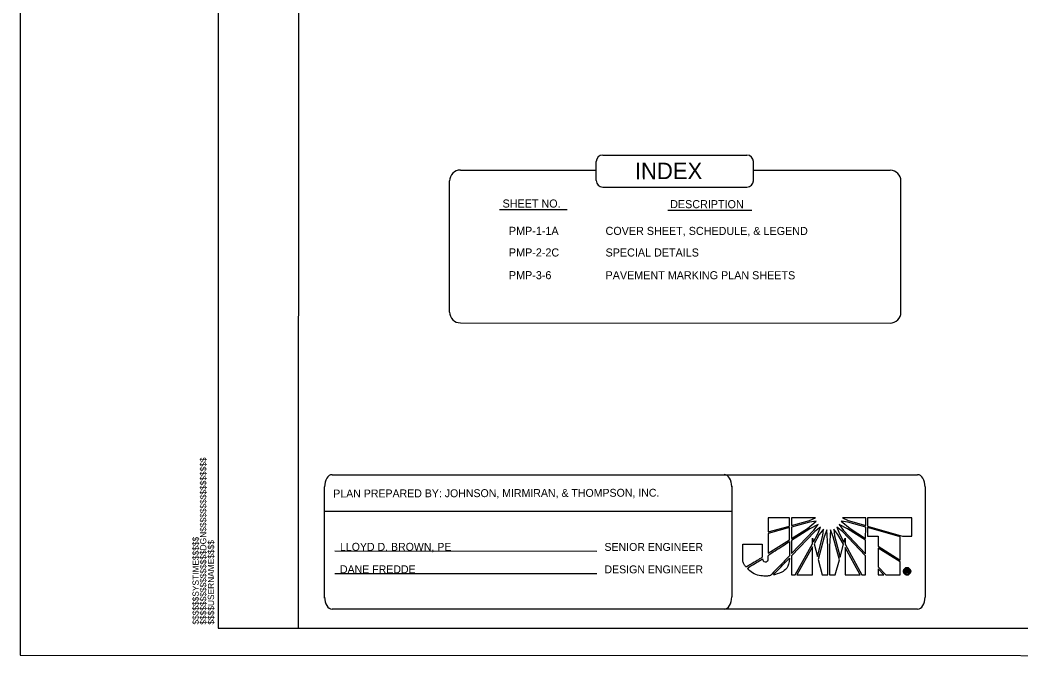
# Model space of a CAD drawing. Extents: x 50667 to 52386, y 46650 to 50479.
# Drawn here: x 50703 to 51544, y 49383 to 49917 of the extents above; entities that cross this region are included whole.
import ezdxf

# ---------------------------------------------------------------- set-up
doc = ezdxf.new("R2010")
doc.units = 0
for name, color, linetype in [('Default', 7, 'Continuous'), ('DEV TUBULAR MARKER SECTIONAL VIEW CELL', 7, 'Continuous'), ('Exist Utilities Power Pole Text Tag Number', 7, 'Continuous'), ('Prop Vertical Profile Ditch Grade Left', 7, 'Continuous'), ('Prop VPI Ditch Grade Left Label', 7, 'Continuous'), ('TSCONFLICT', 7, 'Continuous')]:
    doc.layers.add(name, color=color, linetype=linetype)

msp = doc.modelspace()

# ---------------------------------------------------------------- linework, layer by layer
at = {"layer": 'Default'}
for p, q in [((50965.09, 49534.88), (51457.31, 49534.93)), ((50958.71, 49431.24), (50958.68, 49524.68)), ((51301.08, 49525.65), (51301.1, 49432.21)), ((51463.72, 49524.69), (51463.73, 49432.13)), ((50958.67, 49504.26), (51301.11, 49504.41)), ((51349.65, 49498.59), (51331.88, 49498.58)), ((51331.88, 49498.58), (51331.88, 49486.8)), ((51349.65, 49491.73), (51349.65, 49498.59)), ((51371.49, 49498.68), (51351.5, 49498.68)), ((51351.5, 49498.68), (51351.5, 49492.31)), ((51351.5, 49492.31), (51366.39, 49496.42)), ((51366.39, 49495.04), (51351.5, 49490.93)), ((51364.84, 49489.76), (51372.2, 49495.75)), ((51366.39, 49496.42), (51371.49, 49498.68)), ((51372.2, 49495.75), (51366.39, 49495.04)), ((51373.67, 49492.99), (51366.89, 49489.56)), ((51370.24, 49488.18), (51373.67, 49492.99)), ((51391.58, 49492.99), (51395.01, 49488.09)), ((51398.44, 49489.56), (51391.58, 49492.99)), ((51393.14, 49495.75), (51400.58, 49489.65)), ((51398.62, 49495.04), (51393.14, 49495.75)), ((51413.84, 49498.59), (51394.13, 49498.68)), ((51394.13, 49498.68), (51399.12, 49496.33)), ((51413.84, 49490.85), (51398.62, 49495.04)), ((51399.12, 49496.33), (51413.84, 49492.2)), ((51413.84, 49492.2), (51413.84, 49498.59)), ((51452.57, 49498.69), (51415.22, 49498.68)), ((51415.22, 49498.68), (51415.22, 49491.82)), ((51452.57, 49483.38), (51452.57, 49498.69)), ((51331.88, 49486.8), (51349.65, 49491.73)), ((51349.65, 49490.44), (51331.88, 49485.45)), ((51331.88, 49485.45), (51331.88, 49468.88)), ((51349.65, 49480.14), (51349.65, 49490.44)), ((51351.5, 49490.93), (51351.5, 49481.32)), ((51351.5, 49481.32), (51364.84, 49489.76)), ((51366.89, 49489.56), (51351.5, 49479.76)), ((51351.5, 49468.68), (51370.24, 49488.18)), ((51371, 49487.21), (51351.5, 49466.8)), ((51369.83, 49478.39), (51373.55, 49485.16)), ((51374.75, 49484.75), (51370.32, 49476.71)), ((51375.72, 49490.85), (51371, 49487.21)), ((51373.55, 49485.16), (51375.72, 49490.85)), ((51378.27, 49489.27), (51374.75, 49484.75)), ((51377.77, 49483.78), (51378.27, 49489.27)), ((51381.2, 49488.47), (51378.77, 49482.79)), ((51381.97, 49474.46), (51381.2, 49488.47)), ((51384.13, 49488.47), (51383.23, 49474.46)), ((51386.48, 49482.79), (51384.13, 49488.47)), ((51386.98, 49489.27), (51387.57, 49483.58)), ((51390.41, 49484.75), (51386.98, 49489.27)), ((51389.5, 49490.85), (51391.67, 49485.16)), ((51394.22, 49487.21), (51389.5, 49490.85)), ((51395.01, 49476.42), (51390.41, 49484.75)), ((51391.67, 49485.16), (51395.48, 49478.1)), ((51413.72, 49466.63), (51394.22, 49487.21)), ((51395.01, 49488.09), (51413.72, 49468.48)), ((51413.72, 49479.86), (51398.44, 49489.56)), ((51400.58, 49489.65), (51413.72, 49481.44)), ((51413.72, 49481.44), (51413.84, 49490.85)), ((51415.22, 49491.82), (51415.22, 49491.62)), ((51415.22, 49491.62), (51444.63, 49483.38)), ((51415.22, 49490.56), (51415.22, 49490.44)), ((51442.75, 49482.7), (51415.22, 49490.56)), ((51415.22, 49490.44), (51415.22, 49483.29)), ((51331.88, 49468.88), (51349.65, 49480.14)), ((51351.5, 49479.76), (51351.5, 49468.68)), ((51354.43, 49450.67), (51368.95, 49476.92)), ((51368.95, 49476.92), (51368.95, 49481.61)), ((51368.95, 49481.61), (51369.83, 49478.39)), ((51370.32, 49476.71), (51373.17, 49466.04)), ((51373.17, 49466.04), (51377.77, 49483.78)), ((51378.77, 49482.79), (51373.76, 49463.58)), ((51391.59, 49463.29), (51386.48, 49482.79)), ((51387.57, 49483.58), (51392.17, 49465.63)), ((51392.17, 49465.63), (51395.01, 49476.42)), ((51395.48, 49478.1), (51396.39, 49481.61)), ((51396.39, 49481.61), (51396.39, 49476.42)), ((51396.39, 49476.42), (51410.59, 49450.68)), ((51413.72, 49468.48), (51413.72, 49479.86)), ((51415.22, 49483.29), (51424.34, 49483.29)), ((51424.34, 49483.29), (51424.34, 49474.76)), ((51442.75, 49463.09), (51442.75, 49482.7)), ((51444.63, 49483.38), (51452.57, 49483.38)), ((50967.45, 49470.81), (51187.76, 49470.71)), ((51368.95, 49474.37), (51355.81, 49450.67)), ((51369.07, 49450.68), (51368.95, 49474.37)), ((51381.97, 49450.76), (51381.97, 49474.46)), ((51383.23, 49474.46), (51383.23, 49450.76)), ((51409.12, 49450.77), (51396.39, 49473.87)), ((51396.39, 49473.87), (51396.4, 49450.77)), ((51424.34, 49474.76), (51442.75, 49463.09)), ((51424.34, 49473.29), (51424.34, 49457.4)), ((51442.75, 49461.71), (51424.34, 49473.29)), ((51351.5, 49466.8), (51351.5, 49450.67)), ((51373.76, 49463.58), (51377.1, 49450.76)), ((51388.16, 49450.77), (51391.59, 49463.29)), ((51413.73, 49450.68), (51413.72, 49466.63)), ((51442.75, 49450.68), (51442.75, 49461.71)), ((50967.44, 49451.94), (51187.75, 49451.82)), ((51351.5, 49450.67), (51354.43, 49450.67)), ((51355.81, 49450.67), (51369.07, 49450.68)), ((51377.1, 49450.76), (51381.97, 49450.76)), ((51383.23, 49450.76), (51388.16, 49450.77)), ((51396.4, 49450.77), (51409.12, 49450.77)), ((51410.59, 49450.68), (51413.73, 49450.68)), ((51424.34, 49457.4), (51430.7, 49450.68)), ((51428.94, 49450.68), (51424.34, 49455.67)), ((51424.34, 49455.67), (51424.34, 49450.68)), ((51424.34, 49450.68), (51428.94, 49450.68)), ((51430.7, 49450.68), (51442.75, 49450.68)), ((51447.43, 49452.36), (51447.43, 49455.08)), ((51447.43, 49455.08), (51448.54, 49455.08)), ((51448.05, 49452.36), (51447.43, 49452.36)), ((51448.54, 49454.56), (51448.05, 49454.56)), ((51448.05, 49454.56), (51448.05, 49453.92)), ((51448.05, 49453.92), (51448.54, 49453.92)), ((51448.54, 49453.42), (51448.05, 49453.42)), ((51448.05, 49453.42), (51448.05, 49452.36)), ((51448.54, 49456.68), (51448.54, 49456.12)), ((51448.54, 49456.12), (51448.54, 49456.68)), ((51448.54, 49455.08), (51448.54, 49454.56)), ((51448.54, 49454.56), (51448.54, 49455.08)), ((51448.54, 49455.08), (51448.72, 49455.08)), ((51448.62, 49454.56), (51448.54, 49454.56)), ((51448.54, 49453.92), (51448.54, 49453.42)), ((51448.54, 49453.42), (51448.54, 49453.92)), ((51448.54, 49453.92), (51448.57, 49453.92)), ((51448.57, 49453.42), (51448.54, 49453.42)), ((51448.55, 49451.3), (51448.55, 49450.71)), ((51448.55, 49450.71), (51448.55, 49451.3)), ((51448.55, 49451.3), (51448.57, 49451.3)), ((51448.57, 49450.71), (51448.55, 49450.71)), ((51457.31, 49421.89), (50965.1, 49421.83))]:
    msp.add_line(p, q, dxfattribs=at)
for points in [[(51331.88, 49486.8), (51349.65, 49491.73), (51349.65, 49498.59), (51331.88, 49498.58), (51331.88, 49486.8)], [(51366.39, 49496.42), (51371.49, 49498.68), (51351.5, 49498.68), (51351.5, 49492.31), (51366.39, 49496.42)], [(51351.5, 49490.93), (51351.5, 49481.32), (51364.84, 49489.76), (51372.2, 49495.75), (51366.39, 49495.04), (51351.5, 49490.93)], [(51351.5, 49479.76), (51351.5, 49468.68), (51370.24, 49488.18), (51373.67, 49492.99), (51366.89, 49489.56), (51351.5, 49479.76)], [(51391.58, 49492.99), (51395.01, 49488.09), (51413.72, 49468.48), (51413.72, 49479.86), (51398.44, 49489.56), (51391.58, 49492.99)], [(51393.14, 49495.75), (51400.58, 49489.65), (51413.72, 49481.44), (51413.84, 49490.85), (51398.62, 49495.04), (51393.14, 49495.75)], [(51399.12, 49496.33), (51413.84, 49492.2), (51413.84, 49498.59), (51394.13, 49498.68), (51399.12, 49496.33)], [(51452.57, 49498.69), (51415.22, 49498.68), (51415.22, 49491.82), (51415.22, 49491.62), (51444.63, 49483.38), (51452.57, 49483.38), (51452.57, 49498.69)], [(51331.88, 49468.88), (51349.65, 49480.14), (51349.65, 49490.44), (51331.88, 49485.45), (51331.88, 49468.88)], [(51375.72, 49490.85), (51371, 49487.21), (51351.5, 49466.8), (51351.5, 49450.67), (51354.43, 49450.67), (51368.95, 49476.92), (51368.95, 49481.61), (51369.83, 49478.39), (51373.55, 49485.16), (51375.72, 49490.85)], [(51378.27, 49489.27), (51374.75, 49484.75), (51370.32, 49476.71), (51373.17, 49466.04), (51377.77, 49483.78), (51378.27, 49489.27)], [(51378.77, 49482.79), (51373.76, 49463.58), (51377.1, 49450.76), (51381.97, 49450.76), (51381.97, 49474.46), (51381.2, 49488.47), (51378.77, 49482.79)], [(51384.13, 49488.47), (51383.23, 49474.46), (51383.23, 49450.76), (51388.16, 49450.77), (51391.59, 49463.29), (51386.48, 49482.79), (51384.13, 49488.47)], [(51386.98, 49489.27), (51387.57, 49483.58), (51392.17, 49465.63), (51395.01, 49476.42), (51390.41, 49484.75), (51386.98, 49489.27)], [(51389.5, 49490.85), (51391.67, 49485.16), (51395.48, 49478.1), (51396.39, 49481.61), (51396.39, 49476.42), (51410.59, 49450.68), (51413.73, 49450.68), (51413.72, 49466.63), (51394.22, 49487.21), (51389.5, 49490.85)], [(51415.22, 49490.56), (51415.22, 49490.44), (51415.22, 49483.29), (51424.34, 49483.29), (51424.34, 49474.76), (51442.75, 49463.09), (51442.75, 49482.7), (51415.22, 49490.56)], [(51355.81, 49450.67), (51369.07, 49450.68), (51368.95, 49474.37), (51355.81, 49450.67)], [(51396.4, 49450.77), (51409.12, 49450.77), (51396.39, 49473.87), (51396.4, 49450.77)], [(51424.34, 49473.29), (51424.34, 49457.4), (51430.7, 49450.68), (51442.75, 49450.68), (51442.75, 49461.71), (51424.34, 49473.29), (51424.34, 49473.29)], [(51424.34, 49450.68), (51424.34, 49450.68), (51428.94, 49450.68), (51424.34, 49455.67), (51424.34, 49450.68)], [(51448.54, 49455.08), (51447.43, 49455.08), (51447.43, 49452.36), (51448.05, 49452.36), (51448.05, 49453.42), (51448.54, 49453.42), (51448.54, 49453.92), (51448.05, 49453.92), (51448.05, 49454.56), (51448.54, 49454.56), (51448.54, 49455.08)], [(51449.73, 49453), (51449.73, 49452.86), (51449.75, 49452.76), (51449.75, 49452.66), (51449.83, 49452.36), (51449.26, 49452.36)]]:
    msp.add_lwpolyline(points, dxfattribs=at)
for centre, major_axis, start_param, end_param in [((50965.1, 49524.69), (0, 10.24), 0.000702, 1.571498), ((51294.69, 49524.77), (0, 10.24), 4.713091, 6.283887), ((51457.31, 49524.69), (0, 10.24), 4.713091, 6.283887), ((50965.1, 49432.12), (0, -10.24), 4.713091, 6.283887), ((51294.69, 49432.2), (0, -10.24), 0.000702, 1.571498), ((51457.31, 49432.13), (0, -10.24), 0.000702, 1.571498)]:
    msp.add_ellipse(centre, major_axis=major_axis, ratio=0.62659, start_param=start_param, end_param=end_param, dxfattribs=at)
for points, degree in [([(51326.78, 49476.5), (51326.78, 49476.5), (51310.33, 49476.5), (51310.33, 49476.5), (51310.33, 49476.5), (51310.33, 49466.21), (51310.33, 49466.21), (51310.33, 49466.21), (51310.33, 49465.12), (51310.33, 49465.12), (51310.33, 49461.9), (51311.39, 49459.35), (51313.26, 49457.21), (51313.26, 49457.21), (51326.78, 49465.42), (51326.78, 49465.63), (51326.78, 49465.63), (51326.78, 49476.5), (51326.78, 49476.5)], 3), ([(51326.78, 49476.5), (51326.78, 49476.5), (51310.33, 49476.5), (51310.33, 49476.5), (51310.33, 49476.5), (51310.33, 49466.21), (51310.33, 49466.21), (51310.33, 49466.21), (51310.33, 49465.12), (51310.33, 49465.12), (51310.33, 49461.9), (51311.39, 49459.35), (51313.26, 49457.21), (51313.26, 49457.21), (51326.78, 49465.42), (51326.78, 49465.63), (51326.78, 49465.63), (51326.78, 49476.5), (51326.78, 49476.5)], 3), ([(51329.33, 49461.7), (51328.28, 49461.7), (51327.37, 49462.28), (51326.99, 49464.25), (51326.99, 49464.25), (51314.23, 49456.36), (51314.23, 49456.36), (51318.16, 49452.22), (51324.44, 49449.76), (51329.74, 49449.76), (51331.12, 49449.76), (51332.18, 49449.88), (51333.64, 49450.17), (51333.64, 49450.17), (51349.65, 49466.71), (51349.65, 49466.71), (51349.65, 49466.71), (51349.65, 49478.68), (51349.65, 49478.68), (51349.65, 49478.68), (51331.88, 49467.39), (51331.88, 49467.39), (51331.88, 49462.9), (51330.8, 49461.7), (51329.33, 49461.7)], 3), ([(51329.33, 49461.7), (51328.28, 49461.7), (51327.37, 49462.28), (51326.99, 49464.25), (51326.99, 49464.25), (51314.23, 49456.36), (51314.23, 49456.36), (51318.16, 49452.22), (51324.44, 49449.76), (51329.74, 49449.76), (51331.12, 49449.76), (51332.18, 49449.88), (51333.64, 49450.17), (51333.64, 49450.17), (51349.65, 49466.71), (51349.65, 49466.71), (51349.65, 49466.71), (51349.65, 49478.68), (51349.65, 49478.68), (51349.65, 49478.68), (51331.88, 49467.39), (51331.88, 49467.39), (51331.88, 49462.9), (51330.8, 49461.7), (51329.33, 49461.7)], 3), ([(51349.65, 49464.84), (51349.65, 49464.84), (51335.81, 49450.55), (51335.81, 49450.55), (51342.59, 49452.23), (51349.33, 49456.71), (51349.65, 49464.84)], 3), ([(51349.65, 49464.84), (51349.65, 49464.84), (51335.81, 49450.55), (51335.81, 49450.55), (51342.59, 49452.23), (51349.33, 49456.71), (51349.65, 49464.84)], 3), ([(51448.55, 49450.71), (51447.73, 49450.71), (51447.01, 49451), (51446.42, 49451.6), (51445.83, 49452.16), (51445.53, 49452.88), (51445.53, 49453.72), (51445.53, 49454.56), (51445.83, 49455.28), (51446.42, 49455.82), (51447.01, 49456.39), (51447.7, 49456.68), (51448.54, 49456.68), (51448.54, 49456.68), (51448.54, 49456.12), (51448.54, 49456.12), (51447.88, 49456.12), (51447.31, 49455.89), (51446.84, 49455.45), (51446.37, 49454.98), (51446.12, 49454.39), (51446.12, 49453.72), (51446.12, 49453.05), (51446.37, 49452.46), (51446.84, 49451.99), (51447.31, 49451.52), (51447.88, 49451.3), (51448.55, 49451.3), (51448.55, 49451.3), (51448.55, 49450.71), (51448.55, 49450.71), (51448.55, 49450.71), (51448.55, 49450.71), (51448.55, 49450.71)], 3), ([(51448.55, 49450.71), (51447.73, 49450.71), (51447.01, 49451), (51446.42, 49451.6), (51445.83, 49452.16), (51445.53, 49452.88), (51445.53, 49453.72), (51445.53, 49454.56), (51445.83, 49455.28), (51446.42, 49455.82), (51447.01, 49456.39), (51447.7, 49456.68), (51448.54, 49456.68)], 3), ([(51448.54, 49456.12), (51447.88, 49456.12), (51447.31, 49455.89), (51446.84, 49455.45), (51446.37, 49454.98), (51446.12, 49454.39), (51446.12, 49453.72), (51446.12, 49453.05), (51446.37, 49452.46), (51446.84, 49451.99), (51447.31, 49451.52), (51447.88, 49451.3), (51448.55, 49451.3)], 3), ([(51451.58, 49453.72), (51451.58, 49452.88), (51451.29, 49452.17), (51450.72, 49451.57), (51450.13, 49451), (51449.41, 49450.71), (51448.57, 49450.71), (51448.57, 49450.71), (51448.57, 49450.71), (51448.55, 49450.71), (51448.55, 49450.71), (51448.55, 49451.3), (51448.55, 49451.3), (51448.57, 49451.3), (51448.57, 49451.3), (51448.57, 49451.3), (51449.24, 49451.3), (51449.8, 49451.52), (51450.27, 49451.99), (51450.74, 49452.46), (51450.99, 49453.05), (51450.99, 49453.72), (51450.99, 49454.39), (51450.74, 49454.98), (51450.27, 49455.45), (51449.8, 49455.89), (51449.24, 49456.12), (51448.54, 49456.12), (51448.54, 49456.12), (51448.54, 49456.68), (51448.54, 49456.68), (51449.38, 49456.68), (51450.1, 49456.39), (51450.69, 49455.82), (51451.29, 49455.28), (51451.58, 49454.56), (51451.58, 49453.72), (51451.58, 49453.72), (51451.58, 49453.72), (51451.58, 49453.72)], 3), ([(51448.54, 49456.68), (51449.38, 49456.68), (51450.1, 49456.39), (51450.69, 49455.82), (51451.29, 49455.28), (51451.58, 49454.56), (51451.58, 49453.72)], 3), ([(51448.57, 49451.3), (51449.24, 49451.3), (51449.8, 49451.52), (51450.27, 49451.99), (51450.74, 49452.46), (51450.99, 49453.05), (51450.99, 49453.72), (51450.99, 49454.39), (51450.74, 49454.98), (51450.27, 49455.45), (51449.8, 49455.89), (51449.24, 49456.12), (51448.54, 49456.12)], 3), ([(51448.54, 49453.42), (51448.54, 49453.42), (51448.54, 49453.92), (51448.54, 49453.92), (51448.54, 49453.92), (51448.57, 49453.92), (51448.57, 49453.92), (51448.96, 49453.92), (51449.16, 49454.04), (51449.16, 49454.26), (51449.16, 49454.46), (51448.99, 49454.56), (51448.62, 49454.56), (51448.62, 49454.56), (51448.54, 49454.56), (51448.54, 49454.56), (51448.54, 49454.56), (51448.54, 49455.08), (51448.54, 49455.08), (51448.54, 49455.08), (51448.72, 49455.08), (51448.72, 49455.08), (51449.41, 49455.08), (51449.75, 49454.81), (51449.75, 49454.26), (51449.75, 49454.02), (51449.66, 49453.82), (51449.43, 49453.67), (51449.61, 49453.57), (51449.71, 49453.35), (51449.73, 49453), (51449.73, 49453), (51449.73, 49452.86), (51449.73, 49452.86), (51449.73, 49452.86), (51449.75, 49452.76), (51449.75, 49452.76), (51449.75, 49452.76), (51449.75, 49452.66), (51449.75, 49452.66), (51449.75, 49452.66), (51449.83, 49452.36), (51449.83, 49452.36), (51449.83, 49452.36), (51449.26, 49452.36), (51449.26, 49452.36), (51449.19, 49452.51), (51449.14, 49452.66), (51449.14, 49452.86), (51449.14, 49453.1), (51449.11, 49453.25), (51449.04, 49453.33), (51448.96, 49453.37), (51448.82, 49453.42), (51448.57, 49453.42), (51448.57, 49453.42), (51448.54, 49453.42), (51448.54, 49453.42)], 3), ([(51448.57, 49453.92), (51448.96, 49453.92), (51449.16, 49454.04), (51449.16, 49454.26), (51449.16, 49454.46), (51448.99, 49454.56), (51448.62, 49454.56)], 3), ([(51451.58, 49453.72), (51451.58, 49452.88), (51451.29, 49452.17), (51450.72, 49451.57), (51450.13, 49451), (51449.41, 49450.71), (51448.57, 49450.71)], 3), ([(51449.04, 49453.33), (51448.96, 49453.37), (51448.82, 49453.42), (51448.57, 49453.42)], 2), ([(51448.72, 49455.08), (51449.41, 49455.08), (51449.75, 49454.81), (51449.75, 49454.26), (51449.75, 49454.02), (51449.66, 49453.82), (51449.43, 49453.67)], 3), ([(51449.26, 49452.36), (51449.19, 49452.51), (51449.14, 49452.66), (51449.14, 49452.86), (51449.14, 49453.1), (51449.11, 49453.25), (51449.04, 49453.33)], 3), ([(51449.43, 49453.67), (51449.61, 49453.57), (51449.71, 49453.35), (51449.73, 49453)], 2)]:
    msp.add_open_spline(points, degree=degree, dxfattribs=at)
at = {"layer": 'DEV TUBULAR MARKER SECTIONAL VIEW CELL'}
msp.add_lwpolyline([(52369.04, 50455.98), (50869.05, 50455.87), (50869.12, 49405.87), (52369.12, 49405.98)], close=True, dxfattribs=at)
at = {"layer": 'Exist Utilities Power Pole Text Tag Number'}
msp.add_lwpolyline([(52386.04, 50478.48), (50703.13, 50479.27), (50702.62, 49383.36), (52385.53, 49382.58)], close=True, dxfattribs=at)
at = {"layer": 'Prop VPI Ditch Grade Left Label'}
msp.add_line((50702.62, 49383.36), (50702.62, 49383.36), dxfattribs=at)
at = {"layer": 'TSCONFLICT'}
for p, q in [((51187.13, 49782.09), (51187.14, 49798.11)), ((51319.29, 49782.03), (51319.3, 49798.05)), ((51072.99, 49790.94), (51187.13, 49790.88)), ((51319.29, 49790.82), (51434.35, 49790.77)), ((51063.85, 49671.62), (51063.9, 49781.85)), ((51443.38, 49671.45), (51443.44, 49781.68)), ((51105.9, 49757.88), (51162.76, 49757.85)), ((51247.29, 49757.36), (51317.93, 49757.33)), ((51072.93, 49662.53), (51434.29, 49662.36))]:
    msp.add_line(p, q, dxfattribs=at)
for points in [[(50936.87, 49405.88), (50937.36, 50455.88)], [(51192.59, 49803.56), (51313.84, 49803.51)], [(51192.58, 49776.63), (51313.83, 49776.58)]]:
    msp.add_lwpolyline(points, dxfattribs=at)
for centre, radius, start, end in [((51192.59, 49798.11), 5.45, 89.97341, 179.97341), ((51313.84, 49798.06), 5.45, 359.97341, 89.97341), ((51072.99, 49781.85), 9.09, 89.97341, 179.97341), ((51434.35, 49781.68), 9.09, 359.97341, 89.97341), ((51192.58, 49782.09), 5.45, 179.97341, 269.97341), ((51313.83, 49782.03), 5.45, 269.97341, 359.97341), ((51072.94, 49671.62), 9.09, 179.97341, 269.97341), ((51434.3, 49671.45), 9.09, 269.97341, 359.97341)]:
    msp.add_arc(centre, radius, start, end, dxfattribs=at)

# ---------------------------------------------------------------- texts
at = {"layer": 'Default'}
for s, height, rotation, p in [('INDEX', 13.866, 0.15565, (51219.68, 49783.24)), ('SHEET NO.', 6.771, 359.97341, (51108.38, 49759.45)), ('DESCRIPTION', 6.7709, 359.97341, (51249.32, 49758.93)), ('PMP-1-1A', 6.771, 359.97341, (51113.75, 49736.49)), ('COVER SHEET, SCHEDULE, & LEGEND', 6.7709, 359.97341, (51195, 49736.45)), ('PMP-2-2C', 6.771, 359.97341, (51113.74, 49718.34)), ('SPECIAL DETAILS', 6.7709, 359.97341, (51194.99, 49718.3)), ('PMP-3-6', 6.771, 359.97341, (51113.74, 49699.23)), ('PAVEMENT MARKING PLAN SHEETS', 6.7709, 359.97341, (51194.99, 49699.2)), ('PLAN PREPARED BY: JOHNSON, MIRMIRAN, & THOMPSON, INC.', 6.6381, 0.15565, (50966.06, 49515.74)), ('LLOYD D. BROWN, PE', 6.6381, 359.97341, (50971.67, 49471.02)), ('SENIOR ENGINEER', 6.6381, 359.97341, (51194.1, 49470.91)), ('DANE FREDDE', 6.6381, 359.97341, (50971.66, 49452.15)), ('DESIGN ENGINEER', 6.6381, 359.97341, (51194.09, 49452.05))]:
    msp.add_text(s, height=height, rotation=rotation, dxfattribs=at).set_placement(p)
at = {"layer": 'Prop Vertical Profile Ditch Grade Left'}
for s, p in [('$$$$$$$$$$$$$$$$DGN$$$$$$$$$$$$$$$$', (50859.27, 49408.87)), ('$$$$$$SYSTIME$$$$$', (50852.92, 49408.97)), ('$$$$USERNAME$$$$', (50865.82, 49408.92))]:
    msp.add_text(s, height=5.25, rotation=90.00421, dxfattribs=at).set_placement(p)

doc.saveas('drawing.dxf')
